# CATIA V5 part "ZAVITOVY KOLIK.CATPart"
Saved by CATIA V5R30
Part number: ZAVITOVY KOLIK
Bounding box of the stored display mesh (mm): x -30 to 0, y -6 to 6, z -6 to 6
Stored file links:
  C:\Users\ondra\Desktop\PŘÍLOHA P III\CATIA\ZAVITOVY KOLIK.CATPart
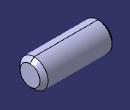
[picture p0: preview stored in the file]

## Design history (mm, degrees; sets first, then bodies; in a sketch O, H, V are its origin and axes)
Set1
  DatumSurface1 to DatumSurface22 "Z35/12x3"
  Plane1: type Offset, RefPlane yz-plane, Offset 15, reversed
  Join1: Elements (DatumSurface1; DatumSurface2; DatumSurface3; DatumSurface4; DatumSurface5; DatumSurface6; DatumSurface7; DatumSurface8; DatumSurface9; DatumSurface10; DatumSurface11; DatumSurface12; DatumSurface13; DatumSurface14; DatumSurface15; DatumSurface16; DatumSurface17; DatumSurface18; DatumSurface19; DatumSurface20; DatumSurface21; DatumSurface22)
Body1 (main body)
  CloseSurface1: CloseElement Join1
